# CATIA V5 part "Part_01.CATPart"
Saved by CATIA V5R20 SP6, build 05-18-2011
Part number: Part_01
Bounding box of the stored display mesh (mm): x -8 to 8, y -23.5 to 0, z 0 to 16.5
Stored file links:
  E:\#01 CATIA Lecture Materials\#16 3D Print Test\3D Print Test\8th Test\Part_01.CATPart
  E:\#01 CATIA Lecture Materials\#16 3D Print Test\3D Print Test\8th Test\Part_02.CATPart
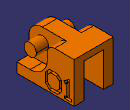
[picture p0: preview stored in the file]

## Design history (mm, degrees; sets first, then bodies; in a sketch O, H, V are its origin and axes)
Set1 "Reference Data"
  Point1 "Center Point": (0, 0, 0)
Body1 (main body)
  Sketch1 on yz-plane, origin (0, 0, 0), H (0, 1, 0), V (0, 0, 1)
    line L1 (0, 0) -> (-23.5, 0)
    line L2 (-23.5, 0) -> (-23.5, 16.5)
    line L3 (-23.5, 16.5) -> (0, 16.5)
    line L4 (0, 16.5) -> (0, 0)
    distance L1 L3 = 16.5
    distance L4 L2 = 23.5
    horizontal: L1 H, L3 H
    vertical: L2 V, L4 V
  Pad1: profile Sketch1, direction (-1, 0, 0), length 8, mirrored extent
  Fillet1: radius 5.5, on edge [face of Pad1 from Sketch1.L3 | face of Pad1 from Sketch1.L2]
  Sketch2 on yz-plane, origin (0, 0, 0), H (0, 1, 0), V (0, 0, 1)
    projected line E1 (0, 16.5) -> (-18, 16.5) from edge [face of Pad1 from Sketch1.L3 | start face of Pad1]
    projected line E2 (-11, 16.5) -> (-23.5, 16.5) from edge [face of Pad1 from Sketch1.L3 | start face of Pad1]
    projected line E3 (-23.5, 11) -> (-23.5, 0) from edge [face of Pad1 from Sketch1.L2 | start face of Pad1]
    projected line E4 (-23.5, 16.5) -> (-23.5, 4) from edge [face of Pad1 from Sketch1.L2 | start face of Pad1]
    point P5 (-11, 16.5)
    line L1 (-11, 16.5) -> (-11, 11)
    line L2 (-18, 4) -> (-23.5, 4)
    point P6 (-23.5, 4)
    reference projected line E5 (-23.5, 0) -> (0, 0) from edge [face of Pad1 from Sketch1.L1 | start face of Pad1]
    arc A1 centre (-18, 11) radius 7 from (-18, 4) to (-11, 11) ccw
    point P10 (-18, 11)
    reference projected line E6 (0, 0) -> (0, 16.5) from edge [face of Pad1 from Sketch1.L4 | start face of Pad1]
    distance E5 L2 = 4
    radius A1 = 7
    distance P10 E6 = 18
    coincidence: P5 E1, P6 E3
    vertical: L1 V
    horizontal: L2 H
    tangency: A1 L2, A1 L1
  Pocket1: profile Sketch2, direction (-1, 0, 0), through (limit type 6), opposite side length -3
  Mirror1: of Pocket1, Sketch2, about yz-plane
  Sketch3 on yz-plane, origin (0, 0, 0), H (0, 1, 0), V (0, 0, 1)
    circle A1 centre (-18, 11) radius 2.5
    point P1 (-18, 11)
    reference projected arc E1 centre (-18, 11) radius 5.5 from (-18, 16.5) to (-23.5, 11) ccw from edge [face of Fillet1 | face of Mirror1]
    radius A1 = 2.5
    concentricity: E1 P1
  Pad2: profile Sketch3, direction (-1, 0, 0), length 8, mirrored extent
  Sketch4 on yz-plane, origin (0, 0, 0), H (0, 1, 0), V (0, 0, 1)
    line L1 (0, 14) -> (-15, 0)
    point P1 (0, 14)
    point P2 (-15, 0)
    reference projected line E1 (0, 16.5) -> (-23.5, 16.5) from edge [face of Pad1 from Sketch1.L3 | start face of Pad1]
    reference projected line E2 (-23.5, 16.5) -> (-23.5, 0) from edge [face of Pad1 from Sketch1.L2 | start face of Pad1]
    distance E1 P1 = 2.5
    distance E2 P2 = 8.5
    coincidence: P1 V, P2 H
  Pocket2: profile Sketch4, direction (-1, 0, 0), length 4, mirrored extent
  Fillet2: radius 3, on edge [face of Pad1 from Sketch1.L3 | face of Pocket1 from Sketch2.L1]; edge [face of Mirror1 | face of Pad1 from Sketch1.L3]
  Sketch5 on start face of Pad1, origin (8, 0, 0), H (0, 1, 0), V (0, 0, 1)
    polyline C1
    polyline C2
    polyline C3
    polyline C4
    point P1 (-2.4878, 7.538)
    point P6 (-2.4878, 7.538)
    coincidence: P1 P6
  Pocket3: profile Sketch5, direction (-1, 0, 0), length 1, thin wall 1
